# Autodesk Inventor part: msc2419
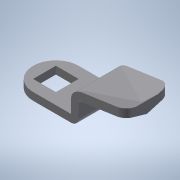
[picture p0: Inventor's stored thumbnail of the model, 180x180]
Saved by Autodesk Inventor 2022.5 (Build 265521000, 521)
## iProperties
Created: 2016-12
Part Number: msc2419
Material: 一般
Document SubType Name: Modeling
Designer: imaocorp
Density: 1 g/cm^3
Appearance: 既定
Author: imaocorp
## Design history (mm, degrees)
node "msc2419.x_t1"
node "msc2419"
node "Base1"
